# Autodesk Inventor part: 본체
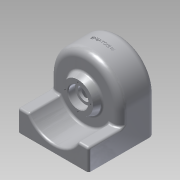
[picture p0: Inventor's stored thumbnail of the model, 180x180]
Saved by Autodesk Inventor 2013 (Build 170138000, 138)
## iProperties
Created: 2015-02
Part Number: 본체
Material: 알루미늄 6061
Document SubType Name: Modeling
Designer: Administrator
Density: 2.71 g/cm^3
Mass: 575.747 g
Surface Area: 706.401 cm^2
Volume: 212.453 cm^3
Author: Administrator
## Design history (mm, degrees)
sketch "스케치1"
  geometry: L1 (0, 0)-(100, 0); L2 (100, 0)-(100, 95); L3 (100, 95)-(0, 95); L4 (0, 95)-(0, 0)
  constraints: 8 end point, 2 parallel, 1 horizontal, 1 perpendicular
  dimensions: "d0" = 100 distance of L1.start L1.end; "d1" = 95 distance of L3.end L1.start
extrude "돌출1" new body sketch "스케치1" distance "d2" = 30; taper "d3" = 0 deg
sketch "스케치2"
  geometry: L1 (0, 0)-(100, 0) reference; L2 (100, 0)-(100, 95) reference; L3 (100, 95)-(0, 95) reference; L4 (0, 95)-(0, 0) reference
node "작업 평면1"
sketch "스케치3"
  geometry: 1 further point
sketch "스케치4"
  geometry: L1 (100, 0)-(0, 0) reference; L2 (0, 0)-(0, 30) reference; L3 (100, 30)-(0, 30) reference; L4 (100, 0)-(100, 30) reference; C1 r 40 at (50, 50); 2 further points
  constraints: 1 centre point, 1 midpoint, 1 vertical alignment
  dimensions: "d5" = 80 diameter of C1; "d6" = 50 distance of point (50, 0) C1.centre
extrude "돌출2" cut sketch "스케치4" stored distance "d7" = 30; taper "d8" = 0 deg
sketch "스케치5"
  geometry: L1 (100, 0)-(0, 0) reference; L2 (0, 0)-(0, 30) reference; L3 (100, 30)-(0, 30) reference; L4 (100, 0)-(100, 30) reference; L5 (0, 50)-(0, 30); L6 (100, 50)-(100, 30); L7 (0, 30)-(100, 30); L8 (0, 30)-(100, 30); A1 r 50 centre (50, 50) between (0, 50) and (100, 50); 2 further points
  constraints: 8 end point, 2 collinear, 2 point on circle, 2 tangent, 1 centre point, 1 midpoint, 1 vertical alignment
  dimensions: "d9" = 100 diameter of A1; "d10" = 50 distance of point (50, 0) A1.centre
extrude "돌출3" join sketch "스케치5" stored distance "d11" = 30; taper "d12" = 0 deg
node "작업 평면2"
sketch "스케치6"
  geometry: L1 (100, 0)-(0, 0) reference; L2 (0, 0)-(0, 50) reference; L3 (100, 0)-(100, 50) reference; L4 (4, 50)-(4, 0); L5 (96, 50)-(96, 0); L6 (4, 0)-(96, 0); A1 r 50 centre (50, 50) between (100, 50) and (0, 50) reference; A2 r 46 centre (50, 50) between (4, 50) and (96, 50); 1 further point
  constraints: 6 end point, 2 perpendicular, 2 point on circle, 2 point on line, 2 tangent, 1 centre point, 1 coincident, 1 collinear
  dimensions: "d13" = 92 diameter of A2
extrude "돌출4" cut sketch "스케치6" stored distance "d14" = 42; taper "d15" = 0 deg
sketch "스케치7"
  geometry: C1 r 25 at (50, 50); A1 r 50 centre (50, 50) between (100, 50) and (0, 50) reference; 1 further point
  constraints: 1 centre point, 1 coincident
  dimensions: "d16" = 50 diameter of C1
extrude "돌출5" join sketch "스케치7" distance "d17" = 10; taper "d18" = 0 deg
sketch "스케치8"
  geometry: C1 r 20 at (50, -50); A1 r 50 centre (50, -50) between (0, -50) and (100, -50) reference
  constraints: 1 centre point, 1 coincident
  dimensions: "d19" = 40 diameter of C1
extrude "돌출6" join sketch "스케치8" distance "d20" = 9; taper "d21" = 0 deg
sketch "스케치9"
  geometry: C1 r 25 at (0, 0) reference; 1 further point
hole "구멍1" sketch "스케치9" at (0, 0) diameter "d22" = 20; stored, may be unused: countersink angle "d26" = 90 deg, drill point angle "d28" = 0 deg; dims "d23" = 6, "d24" = 28, "d25" = 10, "d27" = 8
sketch "스케치10"
  geometry: C1 r 20 at (0, 0) reference; 1 further point
sketch "스케치11"
  geometry: A1 r 46 centre (50, 50) between (96, 50) and (4, 50) reference; 1 further point
hole "구멍2" sketch "스케치11" at (50, 50) diameter "d29" = 20; stored, may be unused: countersink angle "d33" = 90 deg, drill point angle "d35" = 0 deg; dims "d30" = 6, "d31" = 28, "d32" = 8, "d34" = 2
sketch "스케치12"
  geometry: C1 r 14 at (0, 0) reference; C2 r 25 at (0, 0) reference; A1 r 18 centre (0, 0) between (0, 18) and (-18, 0); 3 further points
  constraints: 4 point on circle, 2 horizontal alignment, 1 centre point, 1 coincident, 1 vertical alignment
  dimensions: "d36" = 36 diameter of A1
hole "구멍3" sketch "스케치12" at (0, 18), (-18, 0), (0, -18), (18, 0) diameter "d37" = 2.459; stored, may be unused: countersink angle "d41" = 90 deg, drill point angle "d43" = 0 deg; dims "d38" = 6, "d39" = 28, "d40" = 8, "d42" = 9
sketch "스케치13"
  geometry: L1 (-4, 49)-(-96, 49) reference; L2 (0, 0)-(-100, 0) reference; L3 (-100, 0)-(-100, 95) reference; L4 (-91.75, 9)-(-8.25, 9); 4 further points
  constraints: 3 vertical alignment, 2 end point, 2 horizontal alignment, 2 midpoint, 1 perpendicular
  dimensions: "d44" = 9 distance from line of L4.start L2; "d45" = 83.5 distance of L4.end L4.start; "d46" = 33 distance of L4.start point (-91.75, 42)
hole "구멍4" sketch "스케치13" at (-91.75, 42), (-91.75, 9), (-8.25, 9), (-8.25, 42) diameter "d47" = 5.134; stored, may be unused: countersink angle "d51" = 90 deg, drill point angle "d53" = 0 deg; dims "d48" = 10, "d49" = 28, "d50" = 8, "d52" = 13
node "작업 평면3"
sketch "스케치14"
  geometry: L1 (50, 50)-(-50, 50) reference; L2 (-50, 0)-(-50, 50) reference; L3 (50, 0)-(-50, 0) reference; L4 (50, 0)-(50, 50) reference; 3 further points
  constraints: 1 midpoint, 1 vertical alignment, 1 other
  dimensions: "d54" = 25 distance of point (0, 25) point (0, 50)
feature "엠보싱1" sketch "스케치14" dims "d55" = 0.5, "d56" = 0
fillet "모깎기1" dims "d57" = 10
fillet "모깎기2" dims "d58" = 6
fillet "모깎기3" dims "d59" = 3
fillet "모깎기4" dims "d60" = 3
fillet "모깎기5" dims "d61" = 3
fillet "모깎기6" dims "d62" = 3
feature "면 기울기1" dims angle "d63" = 20 deg
fillet "모깎기7" dims "d64" = 3
fillet "모깎기8" dims "d65" = 3
fillet "모깎기9" dims "d66" = 3
fillet "모깎기10" dims "d67" = 0.3
fillet "모깎기11" dims "d68" = 0.3
fillet "모깎기12" dims "d69" = 3
chamfer "모따기1" distance "d70" = 1; stored, may be unused: second distance "d71" = 2, angle "d72" = 45 deg
chamfer "모따기2" distance "d73" = 1; stored, may be unused: second distance "d74" = 2, angle "d75" = 45 deg
node "솔리드1"
node "투영된 루프1"
node "투영된 루프2"
node "투영된 루프3"
node "투영된 루프4"
